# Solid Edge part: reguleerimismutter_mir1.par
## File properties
Author: KULL
Template: Iso Metric Part.par
Last saved by: KULL
Revision: 2
Application: Solid Edge
Accuracy: 0,990
Username: KULL
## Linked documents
reguleerimismutter.par
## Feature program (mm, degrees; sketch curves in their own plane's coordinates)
part copy "CopiedPart_1"
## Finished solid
Body 1: solid body, 53 faces, 109 edges, 58 vertices.
  Faces by surface: cylinder 25, plane 13, torus 13, spline 2
  Edges by curve: circle 63, line 36, spline 6, intersection 4
Bounding box of the edges (mm; curved faces can reach further): 7.400 x 6.924 x 7.706, from (-346.16, -88.924, 49.5908) to (-338.76, -82.0002, 57.297).
Cylindrical faces by radius (mm): R0.1 x12, R0.3 x6, R1.2428 x1, R2 x2, R2.5057 x1, R3 x2, R3.7 x1
Toroidal faces (ring radius, tube radius in mm): R0.2 r0.1 x6, R0.4 r0.1 x6, R3.6 r0.1 x1
Planar faces by outward normal: oblique 13
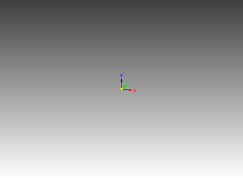
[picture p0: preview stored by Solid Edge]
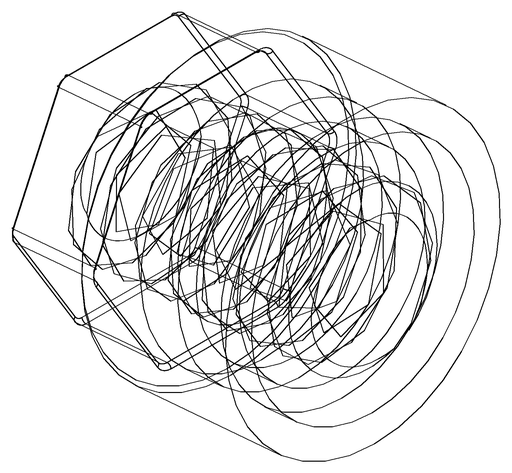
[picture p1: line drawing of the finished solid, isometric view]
